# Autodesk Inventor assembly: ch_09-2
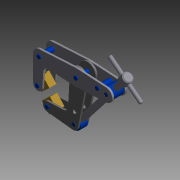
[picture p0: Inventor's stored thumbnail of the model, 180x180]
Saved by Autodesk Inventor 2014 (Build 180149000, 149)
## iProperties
Shininess: 0.0
Length Units: 11272
Angle Units: 11279
Time Units: 11290
Mass Units: 11286
Length Display Precision: 3
Angle Display Precision: 2
Compacted: True
Created: 2000-02
Part Number: ch_09-2
Document SubType Name: Assembly
Designer: Administrator
Mass: 621.139 g
Surface Area: 498.588 cm^2
Volume: 76.8451 cm^3
Density: 8.08301 g/cm^3
Density: 0.0
Volumn: 0.0
Area: 0.0
PropertySet Name: Model Information
Control State: 0
Checked Out: False
Master: False
Author: Administrator
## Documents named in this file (11)
- C:\Users\iTools\Desktop\tutorial files\Assembly FEA 1\analyze-2.iam
- C:\Users\iTools\Desktop\tutorial files\Assembly FEA 1\Upper_Plate.ipt
- C:\Users\iTools\Desktop\tutorial files\Assembly FEA 1\Lower_Plate.ipt
- C:\Users\iTools\Desktop\tutorial files\Assembly FEA 1\Pivot_Threaded.ipt
- C:\Users\iTools\Desktop\tutorial files\Assembly FEA 1\Pivot_Lower.ipt
- C:\Users\iTools\Desktop\tutorial files\Assembly FEA 1\Screw.ipt
- C:\Users\iTools\Desktop\tutorial files\Assembly FEA 1\Pin_A.ipt
- C:\Users\iTools\Desktop\tutorial files\Assembly FEA 1\Pin_B.ipt
- C:\Users\iTools\Desktop\tutorial files\Assembly FEA 1\Handle.ipt
- C:\Users\iTools\Desktop\tutorial files\Assembly FEA 1\SHCS_10-32x6.ipt
- C:\Users\iTools\Desktop\tutorial files\Assembly FEA 1\Grip.ipt
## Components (16 placed, 11 different names)
1. Upper_Plate:1 — Flush:1, Mate:1, Mate:2, Mate:6
2. Upper_Plate:2 — Mate:1, Mate:3, Mate:4, Mate:7, Mate:10, Mate:11, Mate:12, Mate:13, Mate:14, Mate:15, Mate:16, Mate:17
3. Lower_Plate:1 — Mate:2, Mate:5
4. Lower_Plate:2 — Mate:3, Mate:4, Mate:5, Mate:8, Mate:18, Mate:19
5. Pin_A:1 — Mate:10, Mate:14, Mate:24
6. Pin_A:2 — Mate:11, Mate:15
7. Pin_A:3 — Mate:12, Mate:16
8. Pin_A:4 — Mate:13, Mate:17
9. Pin_B:1 — Mate:18, Mate:19, Mate:26
10. Pivot_Threaded:1 — Mate:6, Mate:7, Mate:9
11. Handle:1 — Mate:20, Mate:21, Mate:22
12. Screw:1 — Mate:9, Mate:20, Mate:21, Mate:22, Mate:23, Insert:1, Insert:2
13. Pivot_Lower:1 — Mate:8, Insert:1
14. SHCS_10-32x6:1 — Insert:2
15. ch_09-Upper_Grip.ipt:1 — Mate:24, Mate:25, Mate:27, Angle:1
16. ch_09-Lower_Grip.ipt:1 — Mate:26, Mate:27, Angle:1
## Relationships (31: Mate 27, Insert 2, Flush 1, Angle 1)
- Flush:1: Upper_Plate:1
- Mate:1: Upper_Plate:1 ↔ Upper_Plate:2
- Mate:2: Upper_Plate:1 ↔ Lower_Plate:1
- Mate:3: Upper_Plate:2 ↔ Lower_Plate:2
- Mate:4: Upper_Plate:2 ↔ Lower_Plate:2
- Mate:5: Lower_Plate:1 ↔ Lower_Plate:2
- Mate:6: Upper_Plate:1 ↔ Pivot_Threaded:1
- Mate:7: Upper_Plate:2 ↔ Pivot_Threaded:1
- Mate:8: Lower_Plate:2 ↔ Pivot_Lower:1
- Mate:9: Pivot_Threaded:1 ↔ Screw:1
- Mate:10: Upper_Plate:2 ↔ Pin_A:1
- Mate:11: Upper_Plate:2 ↔ Pin_A:2
- Mate:12: Upper_Plate:2 ↔ Pin_A:3
- Mate:13: Upper_Plate:2 ↔ Pin_A:4
- Mate:14: Upper_Plate:2 ↔ Pin_A:1
- Mate:15: Upper_Plate:2 ↔ Pin_A:2
- Mate:16: Upper_Plate:2 ↔ Pin_A:3
- Mate:17: Upper_Plate:2 ↔ Pin_A:4
- Mate:18: Lower_Plate:2 ↔ Pin_B:1
- Mate:19: Lower_Plate:2 ↔ Pin_B:1
- Mate:20: Handle:1 ↔ Screw:1
- Mate:21: Handle:1 ↔ Screw:1
- Mate:22: Handle:1 ↔ Screw:1
- Mate:23: Screw:1
- Insert:1: Screw:1 ↔ Pivot_Lower:1
- Insert:2: Screw:1 ↔ SHCS_10-32x6:1
- Mate:24: Pin_A:1 ↔ ch_09-Upper_Grip.ipt:1
- Mate:25: ch_09-Upper_Grip.ipt:1
- Mate:26: Pin_B:1 ↔ ch_09-Lower_Grip.ipt:1
- Mate:27: ch_09-Upper_Grip.ipt:1 ↔ ch_09-Lower_Grip.ipt:1
- Angle:1: ch_09-Upper_Grip.ipt:1 ↔ ch_09-Lower_Grip.ipt:1
